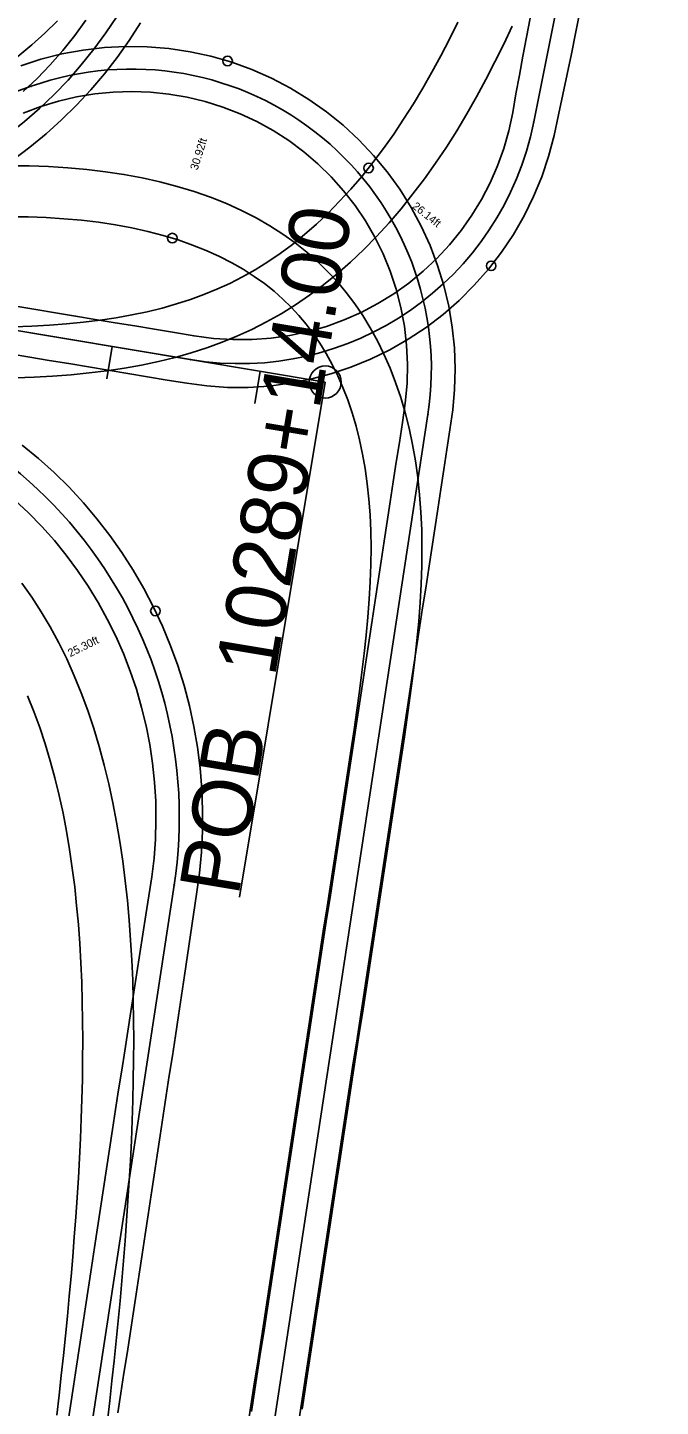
# Model space of a CAD drawing. Extents: x -69 to 14108008, y -6 to 8640172.
# Drawn here: x 14107898.2 to 14108003.8, y 8639717.5 to 8639947.2 of the extents above; entities that cross this region are included whole.
import ezdxf

# ---------------------------------------------------------------- set-up
doc = ezdxf.new("R2010")
doc.units = 0
for name, color, linetype in [('Alignment', 7, 'Continuous'), ('AutoTurn2', 7, 'Continuous'), ('AutoTurn3', 7, 'Continuous'), ('AutoTurn4', 7, 'Continuous'), ('AutoTurn5', 7, 'Continuous'), ('Default', 7, 'Continuous'), ('TextAlignment', 7, 'Continuous'), ('TextAlignmentSml', 7, 'Continuous')]:
    doc.layers.add(name, color=color, linetype=linetype)

msp = doc.modelspace()

# ---------------------------------------------------------------- linework, layer by layer
at = {"layer": 'Alignment'}
msp.add_line((14107947.87, 8639888.18), (14107869.52, 8639901.22), dxfattribs=at)
msp.add_arc((14107846.26, 8640010.61), 75, 302.3186, 340.7615, dxfattribs=at)
at = {"layer": 'AutoTurn2'}
msp.add_line((14107922.68, 8639804.38), (14107890.19, 8639591.46), dxfattribs=at)
for points in [[(14107897.35, 8639877.68), (14107900.05, 8639875.45), (14107902.65, 8639873.11), (14107905.15, 8639870.64), (14107907.54, 8639868.07), (14107909.8, 8639865.4), (14107911.95, 8639862.63), (14107913.98, 8639859.76), (14107915.87, 8639856.81), (14107917.63, 8639853.78), (14107919.25, 8639850.67), (14107920.74, 8639847.49), (14107922.08, 8639844.25), (14107923.28, 8639840.95), (14107924.33, 8639837.6), (14107925.23, 8639834.21), (14107925.97, 8639830.78), (14107926.57, 8639827.33), (14107927.01, 8639823.85), (14107927.29, 8639820.35), (14107927.42, 8639816.84), (14107927.4, 8639813.33), (14107927.21, 8639809.83), (14107926.88, 8639806.34), (14107926.4, 8639802.88), (14107925.91, 8639799.47), (14107925.41, 8639796.07), (14107924.91, 8639792.69), (14107924.4, 8639789.32), (14107923.9, 8639785.97), (14107923.39, 8639782.62), (14107922.89, 8639779.28), (14107922.38, 8639775.95), (14107921.87, 8639772.63), (14107921.37, 8639769.3), (14107920.86, 8639765.99), (14107920.36, 8639762.67), (14107919.85, 8639759.36), (14107919.35, 8639756.05), (14107918.84, 8639752.75), (14107918.34, 8639749.44), (14107917.84, 8639746.14), (14107917.33, 8639742.83), (14107916.83, 8639739.53), (14107916.33, 8639736.23), (14107915.82, 8639732.93), (14107915.32, 8639729.63), (14107914.82, 8639726.33), (14107914.31, 8639723.04), (14107913.81, 8639719.74), (14107913.31, 8639716.44)], [(14107896.08, 8639868.56), (14107898.38, 8639866.4), (14107900.59, 8639864.13), (14107902.7, 8639861.76), (14107904.69, 8639859.31), (14107906.58, 8639856.77), (14107908.35, 8639854.15), (14107910, 8639851.45), (14107911.53, 8639848.68), (14107912.94, 8639845.84), (14107914.21, 8639842.95), (14107915.36, 8639840), (14107916.38, 8639837.01), (14107917.26, 8639833.97), (14107918, 8639830.89), (14107918.61, 8639827.79), (14107919.08, 8639824.66), (14107919.41, 8639821.52), (14107919.6, 8639818.36), (14107919.65, 8639815.2), (14107919.55, 8639812.03), (14107919.32, 8639808.88), (14107918.95, 8639805.74), (14107918.45, 8639802.59), (14107917.94, 8639799.41), (14107917.43, 8639796.21), (14107916.93, 8639793), (14107916.43, 8639789.77), (14107915.93, 8639786.53), (14107915.43, 8639783.29), (14107914.93, 8639780.03), (14107914.43, 8639776.77), (14107913.93, 8639773.51), (14107913.42, 8639770.24), (14107912.92, 8639766.96), (14107912.42, 8639763.68), (14107911.92, 8639760.4), (14107911.42, 8639757.12), (14107910.92, 8639753.83), (14107910.42, 8639750.55), (14107909.92, 8639747.26), (14107909.41, 8639743.97), (14107908.91, 8639740.68), (14107908.41, 8639737.39), (14107907.91, 8639734.1), (14107907.41, 8639730.8), (14107906.9, 8639727.51), (14107906.4, 8639724.22), (14107905.9, 8639720.92), (14107905.4, 8639717.63), (14107904.89, 8639714.33)], [(14107897.26, 8639854.69), (14107898.92, 8639852.35), (14107900.5, 8639849.91), (14107902, 8639847.37), (14107903.43, 8639844.75), (14107904.76, 8639842.04), (14107906.02, 8639839.25), (14107907.19, 8639836.39), (14107908.27, 8639833.46), (14107909.28, 8639830.48), (14107910.2, 8639827.44), (14107911.03, 8639824.35), (14107911.8, 8639821.22), (14107912.48, 8639818.05), (14107913.09, 8639814.85), (14107913.64, 8639811.62), (14107914.11, 8639808.37), (14107914.53, 8639805.1), (14107914.88, 8639801.81), (14107915.18, 8639798.51), (14107915.42, 8639795.19), (14107915.61, 8639791.87), (14107915.76, 8639788.54), (14107915.86, 8639785.21), (14107915.92, 8639781.87), (14107915.94, 8639778.53), (14107915.92, 8639775.18), (14107915.87, 8639771.84), (14107915.79, 8639768.49), (14107915.68, 8639765.15), (14107915.54, 8639761.8), (14107915.38, 8639758.46), (14107915.19, 8639755.12), (14107914.98, 8639751.77), (14107914.75, 8639748.43), (14107914.5, 8639745.09), (14107914.23, 8639741.76), (14107913.95, 8639738.42), (14107913.65, 8639735.09), (14107913.33, 8639731.76), (14107913.01, 8639728.43), (14107912.67, 8639725.1), (14107912.31, 8639721.77), (14107911.95, 8639718.45), (14107911.58, 8639715.13)], [(14107898.21, 8639835.89), (14107899.27, 8639833.29), (14107900.26, 8639830.62), (14107901.18, 8639827.89), (14107902.03, 8639825.08), (14107902.81, 8639822.22), (14107903.51, 8639819.3), (14107904.15, 8639816.34), (14107904.73, 8639813.33), (14107905.24, 8639810.29), (14107905.69, 8639807.21), (14107906.09, 8639804.1), (14107906.42, 8639800.97), (14107906.71, 8639797.81), (14107906.94, 8639794.63), (14107907.13, 8639791.44), (14107907.27, 8639788.22), (14107907.36, 8639785), (14107907.42, 8639781.76), (14107907.44, 8639778.52), (14107907.42, 8639775.26), (14107907.38, 8639772), (14107907.3, 8639768.73), (14107907.19, 8639765.46), (14107907.05, 8639762.18), (14107906.89, 8639758.9), (14107906.71, 8639755.62), (14107906.5, 8639752.33), (14107906.27, 8639749.04), (14107906.03, 8639745.75), (14107905.76, 8639742.46), (14107905.48, 8639739.16), (14107905.18, 8639735.87), (14107904.87, 8639732.57), (14107904.55, 8639729.27), (14107904.21, 8639725.98), (14107903.86, 8639722.68), (14107903.5, 8639719.38), (14107903.13, 8639716.08)]]:
    msp.add_lwpolyline(points, dxfattribs=at)
for centre, radius in [((14107919.56, 8639850.04), 0.8), ((14107922.68, 8639804.38), 0.0417), ((14107922.68, 8639804.38), 0.0417)]:
    msp.add_circle(centre, radius, dxfattribs=at)
msp.add_arc((14107848.54, 8639815.69), 75, 351.3249, 84.5969, dxfattribs=at)
at = {"layer": 'AutoTurn3'}
for p, q in [((14107982.64, 8639931.5), (14108003.76, 8640037.77)), ((14107875.44, 8639900.23), (14107925.39, 8639891.92))]:
    msp.add_line(p, q, dxfattribs=at)
for points in [[(14107895.34, 8639892.87), (14107898.6, 8639892.33), (14107901.86, 8639891.78), (14107905.13, 8639891.24), (14107908.4, 8639890.69), (14107911.67, 8639890.15), (14107914.94, 8639889.6), (14107918.22, 8639889.06), (14107921.5, 8639888.51), (14107924.78, 8639887.97), (14107928.15, 8639887.52), (14107931.57, 8639887.29), (14107935.03, 8639887.29), (14107938.5, 8639887.51), (14107941.97, 8639887.96), (14107945.41, 8639888.64), (14107948.82, 8639889.54), (14107952.16, 8639890.66), (14107955.44, 8639892), (14107958.63, 8639893.55), (14107961.71, 8639895.32), (14107964.67, 8639897.28), (14107967.51, 8639899.44), (14107970.19, 8639901.78), (14107972.72, 8639904.29), (14107975.08, 8639906.97), (14107977.26, 8639909.8), (14107979.24, 8639912.77), (14107981.03, 8639915.87), (14107982.61, 8639919.08), (14107983.97, 8639922.38), (14107985.11, 8639925.77), (14107986.02, 8639929.23), (14107986.78, 8639932.67), (14107987.51, 8639936.09), (14107988.22, 8639939.48), (14107988.91, 8639942.86), (14107989.6, 8639946.22), (14107990.28, 8639949.57)], [(14107895.93, 8639897.35), (14107898.93, 8639897.47), (14107901.87, 8639897.64), (14107904.75, 8639897.86), (14107907.57, 8639898.14), (14107910.33, 8639898.48), (14107913.02, 8639898.88), (14107915.64, 8639899.35), (14107918.19, 8639899.89), (14107920.66, 8639900.5), (14107923.06, 8639901.18), (14107925.38, 8639901.92), (14107927.62, 8639902.74), (14107929.8, 8639903.63), (14107931.95, 8639904.61), (14107934.09, 8639905.69), (14107936.2, 8639906.88), (14107938.28, 8639908.18), (14107940.35, 8639909.58), (14107942.39, 8639911.1), (14107944.4, 8639912.73), (14107946.39, 8639914.47), (14107948.35, 8639916.32), (14107950.27, 8639918.28), (14107952.16, 8639920.33), (14107954, 8639922.49), (14107955.8, 8639924.73), (14107957.56, 8639927.06), (14107959.28, 8639929.47), (14107960.94, 8639931.96), (14107962.56, 8639934.51), (14107964.14, 8639937.13), (14107965.66, 8639939.81), (14107967.14, 8639942.54), (14107968.58, 8639945.32), (14107969.97, 8639948.15)], [(14107896.2, 8639888.85), (14107899.33, 8639888.98), (14107902.42, 8639889.16), (14107905.48, 8639889.39), (14107908.5, 8639889.69), (14107911.47, 8639890.06), (14107914.39, 8639890.49), (14107917.26, 8639891.01), (14107920.07, 8639891.6), (14107922.82, 8639892.28), (14107925.5, 8639893.04), (14107928.11, 8639893.88), (14107930.66, 8639894.8), (14107933.15, 8639895.82), (14107935.63, 8639896.95), (14107938.08, 8639898.19), (14107940.51, 8639899.56), (14107942.9, 8639901.04), (14107945.26, 8639902.65), (14107947.58, 8639904.37), (14107949.86, 8639906.22), (14107952.1, 8639908.17), (14107954.29, 8639910.24), (14107956.43, 8639912.41), (14107958.51, 8639914.68), (14107960.54, 8639917.05), (14107962.5, 8639919.5), (14107964.42, 8639922.03), (14107966.27, 8639924.64), (14107968.06, 8639927.31), (14107969.79, 8639930.04), (14107971.47, 8639932.83), (14107973.09, 8639935.68), (14107974.65, 8639938.56), (14107976.16, 8639941.49), (14107977.62, 8639944.46), (14107979.03, 8639947.45)], [(14107896.3, 8639900.81), (14107899.61, 8639900.26), (14107902.92, 8639899.71), (14107906.23, 8639899.16), (14107909.53, 8639898.61), (14107912.83, 8639898.06), (14107916.13, 8639897.51), (14107919.42, 8639896.97), (14107922.72, 8639896.42), (14107926.01, 8639895.87), (14107929.24, 8639895.44), (14107932.47, 8639895.24), (14107935.67, 8639895.25), (14107938.84, 8639895.48), (14107941.98, 8639895.93), (14107945.06, 8639896.59), (14107948.08, 8639897.45), (14107951.02, 8639898.52), (14107953.88, 8639899.78), (14107956.64, 8639901.23), (14107959.28, 8639902.86), (14107961.81, 8639904.66), (14107964.21, 8639906.63), (14107966.47, 8639908.76), (14107968.58, 8639911.03), (14107970.53, 8639913.43), (14107972.31, 8639915.96), (14107973.91, 8639918.6), (14107975.34, 8639921.34), (14107976.58, 8639924.17), (14107977.63, 8639927.08), (14107978.48, 8639930.04), (14107979.12, 8639933.06), (14107979.67, 8639936.17), (14107980.25, 8639939.31), (14107980.84, 8639942.46), (14107981.44, 8639945.62), (14107982.05, 8639948.81)]]:
    msp.add_lwpolyline(points, dxfattribs=at)
for centre, radius in [((14107982.64, 8639931.5), 0.0417), ((14107982.64, 8639931.5), 0.0417), ((14107955.09, 8639923.82), 0.8), ((14107975.53, 8639907.53), 0.8), ((14107925.39, 8639891.92), 0.0417), ((14107925.39, 8639891.92), 0.0417)]:
    msp.add_circle(centre, radius, dxfattribs=at)
msp.add_arc((14107933.6, 8639941.24), 50, 260.5511, 348.7632, dxfattribs=at)
at = {"layer": 'AutoTurn4'}
for points in [[(14107917.07, 8639948.01), (14107915.19, 8639945.09), (14107913.18, 8639942.25), (14107911.04, 8639939.5), (14107908.78, 8639936.85), (14107906.4, 8639934.29), (14107903.92, 8639931.84), (14107901.32, 8639929.51), (14107898.63, 8639927.28), (14107895.84, 8639925.18)], [(14107903.24, 8639948.33), (14107901.14, 8639946.31), (14107898.93, 8639944.34), (14107896.62, 8639942.42)], [(14107907.96, 8639948.45), (14107906.09, 8639945.89), (14107904.1, 8639943.41), (14107902.01, 8639941.03), (14107899.81, 8639938.75), (14107897.51, 8639936.57)]]:
    msp.add_lwpolyline(points, dxfattribs=at)
msp.add_arc((14107849.76, 8639989.24), 75, 268.0371, 351.4466, dxfattribs=at)
at = {"layer": 'AutoTurn5'}
for p, q in [((14107898.86, 8639937.45), (14107802.12, 8639903.18)), ((14107935.03, 8639686.41), (14107964.99, 8639882.78))]:
    msp.add_line(p, q, dxfattribs=at)
for points in [[(14107943.51, 8639715.46), (14107944.01, 8639718.75), (14107944.51, 8639722.05), (14107945.01, 8639725.34), (14107945.52, 8639728.64), (14107946.02, 8639731.93), (14107946.52, 8639735.23), (14107947.02, 8639738.52), (14107947.53, 8639741.82), (14107948.03, 8639745.11), (14107948.53, 8639748.41), (14107949.03, 8639751.7), (14107949.54, 8639755), (14107950.04, 8639758.29), (14107950.54, 8639761.59), (14107951.05, 8639764.88), (14107951.55, 8639768.18), (14107952.05, 8639771.47), (14107952.55, 8639774.77), (14107953.06, 8639778.06), (14107953.56, 8639781.36), (14107954.06, 8639784.65), (14107954.56, 8639787.95), (14107955.07, 8639791.24), (14107955.57, 8639794.54), (14107956.07, 8639797.83), (14107956.57, 8639801.13), (14107957.08, 8639804.42), (14107957.58, 8639807.72), (14107958.08, 8639811.01), (14107958.59, 8639814.31), (14107959.09, 8639817.6), (14107959.59, 8639820.9), (14107960.09, 8639824.19), (14107960.6, 8639827.49), (14107961.1, 8639830.78), (14107961.6, 8639834.08), (14107962.1, 8639837.37), (14107962.61, 8639840.66), (14107963.11, 8639843.96), (14107963.61, 8639847.25), (14107964.11, 8639850.55), (14107964.62, 8639853.84), (14107965.12, 8639857.14), (14107965.62, 8639860.43), (14107966.13, 8639863.73), (14107966.63, 8639867.02), (14107967.13, 8639870.32), (14107967.63, 8639873.61), (14107968.14, 8639876.91), (14107968.64, 8639880.2), (14107969.13, 8639883.53), (14107969.44, 8639886.94), (14107969.53, 8639890.39), (14107969.4, 8639893.87), (14107969.04, 8639897.34), (14107968.45, 8639900.8), (14107967.64, 8639904.23), (14107966.6, 8639907.6), (14107965.34, 8639910.91), (14107963.86, 8639914.14), (14107962.18, 8639917.27), (14107960.28, 8639920.29), (14107958.2, 8639923.17), (14107955.92, 8639925.92), (14107953.46, 8639928.51), (14107950.84, 8639930.94), (14107948.06, 8639933.19), (14107945.14, 8639935.25), (14107942.08, 8639937.12), (14107938.91, 8639938.78), (14107935.63, 8639940.22), (14107932.27, 8639941.44), (14107928.82, 8639942.44), (14107925.32, 8639943.21), (14107921.78, 8639943.74), (14107918.2, 8639944.03), (14107914.62, 8639944.09), (14107911.04, 8639943.91), (14107907.48, 8639943.48), (14107903.95, 8639942.83), (14107900.47, 8639941.94), (14107897.09, 8639940.85)], [(14107935.6, 8639716.67), (14107936.1, 8639719.96), (14107936.6, 8639723.26), (14107937.1, 8639726.55), (14107937.61, 8639729.84), (14107938.11, 8639733.14), (14107938.61, 8639736.43), (14107939.12, 8639739.73), (14107939.62, 8639743.02), (14107940.12, 8639746.32), (14107940.62, 8639749.61), (14107941.13, 8639752.91), (14107941.63, 8639756.2), (14107942.13, 8639759.5), (14107942.63, 8639762.79), (14107943.14, 8639766.09), (14107943.64, 8639769.38), (14107944.14, 8639772.68), (14107944.64, 8639775.97), (14107945.15, 8639779.27), (14107945.65, 8639782.56), (14107946.15, 8639785.86), (14107946.66, 8639789.15), (14107947.16, 8639792.45), (14107947.66, 8639795.74), (14107948.16, 8639799.04), (14107948.67, 8639802.33), (14107949.17, 8639805.63), (14107949.67, 8639808.92), (14107950.17, 8639812.22), (14107950.68, 8639815.51), (14107951.18, 8639818.81), (14107951.68, 8639822.1), (14107952.18, 8639825.4), (14107952.69, 8639828.69), (14107953.19, 8639831.99), (14107953.69, 8639835.28), (14107954.2, 8639838.58), (14107954.7, 8639841.87), (14107955.2, 8639845.17), (14107955.7, 8639848.46), (14107956.21, 8639851.76), (14107956.71, 8639855.05), (14107957.21, 8639858.35), (14107957.71, 8639861.64), (14107958.22, 8639864.94), (14107958.72, 8639868.23), (14107959.22, 8639871.53), (14107959.72, 8639874.82), (14107960.23, 8639878.12), (14107960.73, 8639881.41), (14107961.21, 8639884.68), (14107961.51, 8639887.91), (14107961.58, 8639891.13), (14107961.43, 8639894.32), (14107961.07, 8639897.48), (14107960.49, 8639900.59), (14107959.71, 8639903.64), (14107958.72, 8639906.62), (14107957.53, 8639909.51), (14107956.15, 8639912.31), (14107954.58, 8639915.01), (14107952.84, 8639917.59), (14107950.93, 8639920.04), (14107948.86, 8639922.36), (14107946.64, 8639924.53), (14107944.28, 8639926.54), (14107941.79, 8639928.39), (14107939.19, 8639930.06), (14107936.48, 8639931.56), (14107933.67, 8639932.87), (14107930.79, 8639933.99), (14107927.84, 8639934.91), (14107924.83, 8639935.63), (14107921.79, 8639936.15), (14107918.71, 8639936.47), (14107915.62, 8639936.58), (14107912.53, 8639936.48), (14107909.46, 8639936.18), (14107906.41, 8639935.67), (14107903.41, 8639934.96), (14107900.45, 8639934.05), (14107897.53, 8639932.96)], [(14107944, 8639717.06), (14107944.51, 8639720.36), (14107945.01, 8639723.65), (14107945.51, 8639726.95), (14107946.01, 8639730.24), (14107946.52, 8639733.54), (14107947.02, 8639736.83), (14107947.52, 8639740.13), (14107948.02, 8639743.42), (14107948.53, 8639746.72), (14107949.03, 8639750.01), (14107949.53, 8639753.31), (14107950.03, 8639756.6), (14107950.54, 8639759.9), (14107951.04, 8639763.19), (14107951.54, 8639766.49), (14107952.05, 8639769.78), (14107952.55, 8639773.08), (14107953.05, 8639776.37), (14107953.55, 8639779.67), (14107954.06, 8639782.96), (14107954.56, 8639786.26), (14107955.06, 8639789.55), (14107955.56, 8639792.85), (14107956.07, 8639796.14), (14107956.57, 8639799.43), (14107957.07, 8639802.73), (14107957.57, 8639806.02), (14107958.08, 8639809.32), (14107958.58, 8639812.61), (14107959.08, 8639815.91), (14107959.59, 8639819.21), (14107960.09, 8639822.5), (14107960.59, 8639825.79), (14107961.07, 8639829.06), (14107961.55, 8639832.31), (14107962, 8639835.55), (14107962.42, 8639838.77), (14107962.81, 8639841.97), (14107963.15, 8639845.14), (14107963.45, 8639848.29), (14107963.69, 8639851.42), (14107963.86, 8639854.51), (14107963.97, 8639857.57), (14107964, 8639860.59), (14107963.95, 8639863.57), (14107963.83, 8639866.52), (14107963.61, 8639869.41), (14107963.31, 8639872.26), (14107962.92, 8639875.05), (14107962.44, 8639877.79), (14107961.87, 8639880.47), (14107961.21, 8639883.08), (14107960.46, 8639885.62), (14107959.61, 8639888.09), (14107958.68, 8639890.49), (14107957.66, 8639892.8), (14107956.56, 8639895.04), (14107955.38, 8639897.18), (14107954.12, 8639899.24), (14107952.78, 8639901.2), (14107951.37, 8639903.07), (14107949.9, 8639904.84), (14107948.31, 8639906.56), (14107946.62, 8639908.22), (14107944.8, 8639909.82), (14107942.87, 8639911.35), (14107940.81, 8639912.82), (14107938.63, 8639914.21), (14107936.33, 8639915.53), (14107933.91, 8639916.76), (14107931.38, 8639917.9), (14107928.74, 8639918.95), (14107926.01, 8639919.91), (14107923.2, 8639920.77), (14107920.3, 8639921.53), (14107917.34, 8639922.19), (14107914.31, 8639922.75), (14107911.23, 8639923.22), (14107908.1, 8639923.59), (14107904.94, 8639923.87), (14107901.74, 8639924.06), (14107898.51, 8639924.17), (14107895.27, 8639924.2)], [(14107935.1, 8639715.05), (14107935.6, 8639718.34), (14107936.1, 8639721.64), (14107936.61, 8639724.93), (14107937.11, 8639728.23), (14107937.61, 8639731.52), (14107938.11, 8639734.82), (14107938.62, 8639738.11), (14107939.12, 8639741.41), (14107939.62, 8639744.7), (14107940.12, 8639748), (14107940.63, 8639751.29), (14107941.13, 8639754.59), (14107941.63, 8639757.88), (14107942.13, 8639761.18), (14107942.64, 8639764.47), (14107943.14, 8639767.77), (14107943.64, 8639771.06), (14107944.15, 8639774.36), (14107944.65, 8639777.65), (14107945.15, 8639780.95), (14107945.65, 8639784.24), (14107946.16, 8639787.54), (14107946.66, 8639790.83), (14107947.16, 8639794.13), (14107947.66, 8639797.42), (14107948.17, 8639800.72), (14107948.67, 8639804.01), (14107949.17, 8639807.31), (14107949.67, 8639810.6), (14107950.18, 8639813.9), (14107950.68, 8639817.19), (14107951.18, 8639820.49), (14107951.68, 8639823.78), (14107952.18, 8639827.05), (14107952.67, 8639830.3), (14107953.13, 8639833.52), (14107953.58, 8639836.7), (14107953.99, 8639839.84), (14107954.37, 8639842.95), (14107954.7, 8639846.01), (14107954.98, 8639849.02), (14107955.21, 8639851.99), (14107955.37, 8639854.91), (14107955.47, 8639857.77), (14107955.5, 8639860.58), (14107955.46, 8639863.34), (14107955.34, 8639866.04), (14107955.15, 8639868.67), (14107954.88, 8639871.24), (14107954.53, 8639873.75), (14107954.1, 8639876.18), (14107953.59, 8639878.55), (14107953.01, 8639880.84), (14107952.35, 8639883.06), (14107951.62, 8639885.19), (14107950.82, 8639887.25), (14107949.95, 8639889.23), (14107949.02, 8639891.12), (14107948.02, 8639892.92), (14107946.97, 8639894.64), (14107945.86, 8639896.27), (14107944.7, 8639897.81), (14107943.49, 8639899.26), (14107942.2, 8639900.65), (14107940.82, 8639902), (14107939.34, 8639903.31), (14107937.74, 8639904.57), (14107936.04, 8639905.78), (14107934.21, 8639906.95), (14107932.27, 8639908.06), (14107930.21, 8639909.1), (14107928.04, 8639910.09), (14107925.75, 8639911), (14107923.36, 8639911.84), (14107920.87, 8639912.59), (14107918.29, 8639913.27), (14107915.62, 8639913.86), (14107912.89, 8639914.37), (14107910.08, 8639914.79), (14107907.21, 8639915.13), (14107904.3, 8639915.39), (14107901.33, 8639915.57), (14107898.33, 8639915.67), (14107895.29, 8639915.7)]]:
    msp.add_lwpolyline(points, dxfattribs=at)
for centre, radius in [((14107931.58, 8639941.66), 0.8), ((14107898.86, 8639937.45), 0.0417), ((14107898.86, 8639937.45), 0.0417), ((14107922.37, 8639912.15), 0.8), ((14107964.99, 8639882.78), 0.0417), ((14107964.99, 8639882.78), 0.0417)]:
    msp.add_circle(centre, radius, dxfattribs=at)
msp.add_arc((14107915.56, 8639890.32), 50, 351.326, 109.5068, dxfattribs=at)
at = {"layer": 'Default'}
msp.add_line((14107947.87, 8639888.18), (14107869.52, 8639901.22), dxfattribs=at)
at = {"layer": 'TextAlignment'}
msp.add_line((14107947.87, 8639888.18), (14107933.58, 8639802.36), dxfattribs=at)
msp.add_circle((14107947.87, 8639888.18), 2.67, dxfattribs=at)
at = {"layer": 'TextAlignmentSml'}
for p, q in [((14107912.36, 8639894.09), (14107911.46, 8639888.7)), ((14107937.02, 8639889.98), (14107936.12, 8639884.6))]:
    msp.add_line(p, q, dxfattribs=at)

# ---------------------------------------------------------------- texts
at = {"layer": 'AutoTurn2'}
msp.add_text('25.30ft', height=1.333, rotation=26.1334, dxfattribs=at).set_placement((14107905.36, 8639842.33))
at = {"layer": 'AutoTurn3'}
msp.add_text('26.14ft', height=1.333, rotation=321.44, dxfattribs=at).set_placement((14107962.26, 8639917.25))
at = {"layer": 'AutoTurn5'}
msp.add_text('30.92ft', height=1.333, rotation=72.6702, dxfattribs=at).set_placement((14107926.57, 8639923.37))
at = {"layer": 'TextAlignment'}
for s, p in [('10289+14.00', (14107939.47, 8639838.91)), ('POB ', (14107933.39, 8639802.39))]:
    msp.add_text(s, height=10.02, rotation=80.5511, dxfattribs=at).set_placement(p)

doc.saveas('drawing.dxf')
